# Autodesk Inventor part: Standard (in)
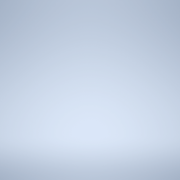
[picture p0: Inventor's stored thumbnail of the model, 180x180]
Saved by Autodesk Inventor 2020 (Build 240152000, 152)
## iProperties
Created: 2019-02
Part Number: Standard (in)
Material: Ogólny
Document SubType Name: Modeling
Density: 1 g/cm^3
Appearance: Domyślna
Designer: F.Stasiak
Manager: www.cadconsulting.pl
Company: Fabian Stasiak CAD Consulting
Subject: Zbiór ćwiczeń. Autodesk Inventor 2020. Kurs podstawowy
Author: F.Stasiak
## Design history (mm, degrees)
